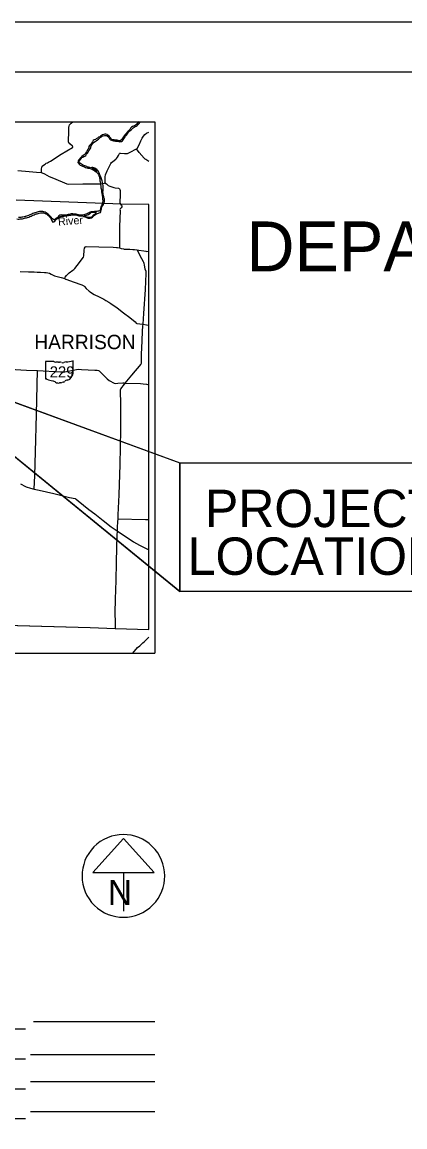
# Model space of a CAD drawing. Extents: x 41.3 to 81.6, y -19.3 to 2.7.
# Drawn here: x 48.93 to 52.78, y -8.35 to 2.73 of the extents above; entities that cross this region are included whole.
import ezdxf

# ---------------------------------------------------------------- set-up
doc = ezdxf.new("R2010")
doc.units = 0
for name, color, linetype in [('Default', 7, 'Continuous'), ('GM_X_County_Road', 7, 'Continuous'), ('GM_X_Major_River', 7, 'Continuous'), ('GM_X_Major_River_Text', 7, 'Continuous'), ('GM_X_State_Route', 7, 'Continuous'), ('GM_X_State_Shield', 7, 'Continuous'), ('GM_X_Township', 7, 'Continuous'), ('GM_X_Township_Road', 7, 'Continuous'), ('GM_X_Township_Text', 7, 'Continuous'), ('GM_X_US_Route', 7, 'Continuous'), ('SH_Border', 7, 'Continuous'), ('SH_Cut_Line', 7, 'Continuous'), ('SH_Data', 7, 'Continuous')]:
    doc.layers.add(name, color=color, linetype=linetype)

msp = doc.modelspace()

# ---------------------------------------------------------------- linework, layer by layer
at = {"layer": 'Default'}
for p, q in [((47.64, -0.634), (50.517, -2.978)), ((47.651, -0.639), (50.517, -1.686))]:
    msp.add_line(p, q, dxfattribs=at)
msp.add_lwpolyline([(47.698, -0.656), (50.517, -1.686), (50.517, -2.978), (47.688, -0.673)], dxfattribs=at)
msp.add_lwpolyline([(50.517, -1.686), (53.875, -1.686), (53.875, -2.978), (50.517, -2.978)], close=True, dxfattribs=at)
at = {"layer": 'GM_X_County_Road'}
for points in [[(48.889, 1.246), (49.003, 1.236), (49.078, 1.23), (49.123, 1.225), (49.128, 1.225), (49.128, 1.26), (49.129, 1.279), (49.13, 1.283), (49.133, 1.288), (49.147, 1.298), (49.164, 1.31), (49.173, 1.317), (49.187, 1.323), (49.197, 1.328), (49.216, 1.339), (49.326, 1.408), (49.438, 1.476), (49.44, 1.479), (49.441, 1.482), (49.438, 1.489), (49.413, 1.513), (49.4, 1.525), (49.397, 1.528), (49.402, 1.647), (49.403, 1.681), (49.403, 1.684), (49.405, 1.691), (49.409, 1.702), (49.417, 1.712), (49.426, 1.72), (49.441, 1.734), (49.441, 1.734)], [(50.204, 1.336), (50.173, 1.356), (50.168, 1.36), (50.158, 1.37), (50.109, 1.426), (50.081, 1.461), (50.086, 1.466), (50.107, 1.504), (50.125, 1.544), (50.136, 1.569), (50.15, 1.588), (50.165, 1.607), (50.18, 1.618), (50.204, 1.629)], [(48.912, 0.232), (48.996, 0.229), (49.053, 0.227), (49.083, 0.226), (49.118, 0.224), (49.158, 0.223), (49.175, 0.223), (49.189, 0.22), (49.208, 0.214), (49.223, 0.206), (49.232, 0.201), (49.243, 0.194), (49.256, 0.189), (49.286, 0.181), (49.326, 0.172), (49.362, 0.163), (49.372, 0.156), (49.383, 0.152), (49.445, 0.129), (49.531, 0.099), (49.545, 0.093), (49.551, 0.089), (49.558, 0.083), (49.577, 0.063), (49.606, 0.035), (49.614, 0.028), (49.62, 0.024), (49.655, 0.002), (49.706, -0.023), (49.753, -0.047), (49.774, -0.058), (49.803, -0.076), (49.822, -0.088), (49.886, -0.134), (49.951, -0.181), (50.014, -0.229), (50.066, -0.274), (50.079, -0.286), (50.085, -0.289), (50.088, -0.29), (50.115, -0.293), (50.143, -0.297), (50.18, -0.302), (50.204, -0.305)], [(48.917, -1.899), (48.966, -1.926), (48.972, -1.928), (49.017, -1.94), (49.055, -1.95), (49.103, -1.961), (49.252, -1.996), (49.408, -2.034), (49.464, -2.046), (49.469, -2.047), (49.475, -2.051), (49.494, -2.067), (49.602, -2.154), (49.662, -2.199), (49.747, -2.265), (49.826, -2.328), (49.885, -2.369), (50.052, -2.479), (50.112, -2.512), (50.204, -2.56)], [(48.645, -3.311), (49.008, -3.322), (49.617, -3.339), (49.866, -3.349), (50.204, -3.358)]]:
    msp.add_lwpolyline(points, dxfattribs=at)
at = {"layer": 'GM_X_Major_River'}
msp.add_line((49.533, 1.386), (49.516, 1.368), dxfattribs=at)
for points in [[(50.106, 1.734), (50.098, 1.725), (50.089, 1.715), (50.082, 1.705), (50.071, 1.699), (50.061, 1.694), (50.051, 1.69), (50.04, 1.685), (50.03, 1.68), (50.021, 1.669), (50.015, 1.658), (50.006, 1.648), (49.996, 1.638), (49.986, 1.629), (49.976, 1.617), (49.966, 1.606), (49.957, 1.594), (49.949, 1.583), (49.942, 1.573), (49.937, 1.563), (49.931, 1.552), (49.921, 1.546), (49.917, 1.544)], [(49.924, 1.535), (49.929, 1.536), (49.939, 1.543), (49.947, 1.554), (49.954, 1.564), (49.962, 1.576), (49.969, 1.588), (49.979, 1.6), (49.987, 1.611), (49.995, 1.621), (50.004, 1.633), (50.014, 1.643), (50.026, 1.654), (50.036, 1.664), (50.046, 1.673), (50.057, 1.679), (50.067, 1.685), (50.078, 1.689), (50.087, 1.696), (50.097, 1.705), (50.106, 1.715), (50.113, 1.725), (50.12, 1.734)], [(49.737, 1.14), (49.733, 1.151), (49.729, 1.161), (49.726, 1.171), (49.721, 1.181), (49.716, 1.192), (49.712, 1.202), (49.708, 1.213), (49.699, 1.234), (49.692, 1.244), (49.684, 1.254), (49.673, 1.262), (49.663, 1.269), (49.654, 1.273), (49.643, 1.274), (49.632, 1.274), (49.622, 1.272), (49.611, 1.274), (49.6, 1.277), (49.59, 1.28), (49.581, 1.284), (49.572, 1.287), (49.561, 1.292), (49.551, 1.295), (49.54, 1.303), (49.529, 1.31), (49.519, 1.316), (49.509, 1.326), (49.504, 1.337), (49.508, 1.348), (49.519, 1.357), (49.524, 1.365), (49.532, 1.376), (49.543, 1.379), (49.552, 1.384), (49.562, 1.388), (49.572, 1.397), (49.579, 1.408), (49.589, 1.419), (49.596, 1.43), (49.603, 1.441), (49.61, 1.452), (49.617, 1.463), (49.621, 1.471), (49.623, 1.481), (49.627, 1.493), (49.632, 1.503), (49.638, 1.514), (49.647, 1.523), (49.658, 1.532), (49.666, 1.536), (49.677, 1.544), (49.688, 1.553), (49.698, 1.56), (49.706, 1.567), (49.717, 1.577), (49.728, 1.584), (49.736, 1.588), (49.747, 1.592), (49.758, 1.595), (49.768, 1.597), (49.778, 1.596), (49.789, 1.591), (49.799, 1.583), (49.807, 1.573), (49.811, 1.563), (49.819, 1.552), (49.83, 1.548), (49.84, 1.547), (49.851, 1.543), (49.86, 1.542), (49.869, 1.54), (49.88, 1.541), (49.892, 1.54), (49.903, 1.536), (49.914, 1.533), (49.924, 1.535)], [(49.917, 1.544), (49.907, 1.543), (49.897, 1.545), (49.887, 1.549), (49.876, 1.551), (49.865, 1.55), (49.855, 1.552), (49.847, 1.553), (49.837, 1.554), (49.826, 1.56), (49.822, 1.571), (49.814, 1.581), (49.805, 1.591), (49.794, 1.6), (49.785, 1.606), (49.774, 1.608), (49.763, 1.609), (49.752, 1.607), (49.741, 1.602), (49.73, 1.595), (49.72, 1.588), (49.711, 1.584), (49.7, 1.578), (49.689, 1.571), (49.677, 1.562), (49.668, 1.557), (49.656, 1.552), (49.646, 1.545), (49.64, 1.534), (49.632, 1.524), (49.626, 1.514), (49.619, 1.505), (49.609, 1.495), (49.603, 1.485), (49.601, 1.475), (49.597, 1.464), (49.592, 1.456), (49.586, 1.445), (49.58, 1.433), (49.573, 1.422), (49.565, 1.411), (49.555, 1.401), (49.544, 1.395), (49.533, 1.386)], [(49.516, 1.368), (49.508, 1.358), (49.499, 1.348), (49.494, 1.338), (49.492, 1.327), (49.497, 1.317), (49.506, 1.307), (49.516, 1.299), (49.526, 1.294), (49.537, 1.289), (49.549, 1.286), (49.56, 1.281), (49.57, 1.276), (49.582, 1.273), (49.593, 1.269), (49.604, 1.268), (49.615, 1.266), (49.626, 1.263), (49.635, 1.259), (49.646, 1.252), (49.654, 1.248), (49.664, 1.241), (49.675, 1.233), (49.684, 1.224), (49.693, 1.215), (49.7, 1.205), (49.702, 1.195), (49.705, 1.184), (49.709, 1.173), (49.712, 1.162)], [(49.684, 1.235), (49.677, 1.247), (49.665, 1.256), (49.653, 1.262), (49.641, 1.268), (49.636, 1.267)], [(49.636, 1.267), (49.641, 1.259), (49.653, 1.251), (49.668, 1.242), (49.68, 1.234), (49.684, 1.235)], [(49.712, 1.162), (49.713, 1.152), (49.714, 1.141), (49.715, 1.133), (49.719, 1.123), (49.72, 1.112), (49.724, 1.08), (49.724, 1.071), (49.726, 1.061), (49.728, 1.05), (49.729, 1.038), (49.73, 1.027), (49.733, 1.016), (49.736, 1.005), (49.737, 0.993), (49.739, 0.983), (49.74, 0.975), (49.74, 0.964), (49.741, 0.956), (49.742, 0.946), (49.742, 0.934), (49.741, 0.926), (49.738, 0.913), (49.734, 0.903), (49.728, 0.892), (49.724, 0.882), (49.722, 0.873), (49.72, 0.863), (49.715, 0.852), (49.711, 0.841), (49.703, 0.837), (49.692, 0.837), (49.681, 0.835), (49.67, 0.834), (49.66, 0.834), (49.648, 0.831), (49.638, 0.83), (49.627, 0.831), (49.616, 0.826), (49.606, 0.819), (49.595, 0.816), (49.584, 0.812), (49.573, 0.807), (49.562, 0.804), (49.552, 0.8), (49.541, 0.797), (49.53, 0.796), (49.519, 0.796), (49.508, 0.798), (49.498, 0.8), (49.486, 0.803), (49.476, 0.806), (49.465, 0.808), (49.443, 0.812), (49.434, 0.812), (49.426, 0.81), (49.416, 0.807), (49.405, 0.805), (49.394, 0.803), (49.385, 0.8), (49.375, 0.798), (49.365, 0.798), (49.354, 0.797), (49.343, 0.798), (49.334, 0.798), (49.323, 0.8), (49.312, 0.798), (49.301, 0.791), (49.293, 0.78), (49.283, 0.771), (49.271, 0.761), (49.26, 0.754), (49.25, 0.751), (49.238, 0.759), (49.232, 0.768), (49.224, 0.778), (49.215, 0.788), (49.205, 0.796), (49.194, 0.806), (49.184, 0.814), (49.173, 0.821), (49.163, 0.826), (49.152, 0.831), (49.141, 0.834), (49.129, 0.835), (49.118, 0.835), (49.107, 0.835), (49.094, 0.831), (49.083, 0.828), (49.072, 0.825), (49.061, 0.821), (49.049, 0.816), (49.041, 0.813), (49.03, 0.808), (49.019, 0.803), (49.01, 0.799), (48.997, 0.795), (48.987, 0.79), (48.975, 0.788), (48.967, 0.784), (48.964, 0.783)], [(49.02, 0.786), (49.022, 0.788), (49.033, 0.793), (49.043, 0.798), (49.053, 0.801), (49.064, 0.806), (49.074, 0.809), (49.084, 0.812), (49.095, 0.815), (49.105, 0.817), (49.116, 0.819), (49.126, 0.821), (49.137, 0.822), (49.147, 0.82), (49.158, 0.817), (49.169, 0.812), (49.179, 0.806), (49.19, 0.798), (49.2, 0.789), (49.211, 0.778), (49.22, 0.768), (49.224, 0.757), (49.229, 0.746), (49.233, 0.736), (49.24, 0.728), (49.251, 0.73), (49.262, 0.738), (49.269, 0.748), (49.28, 0.759), (49.29, 0.763), (49.3, 0.771), (49.31, 0.781), (49.322, 0.787), (49.332, 0.787), (49.343, 0.788), (49.354, 0.787), (49.365, 0.789), (49.377, 0.792), (49.387, 0.794), (49.398, 0.795), (49.41, 0.796), (49.42, 0.798), (49.43, 0.801), (49.441, 0.801), (49.451, 0.802), (49.461, 0.801), (49.469, 0.8), (49.481, 0.798), (49.492, 0.794), (49.503, 0.791), (49.514, 0.791), (49.525, 0.791), (49.535, 0.791), (49.543, 0.79), (49.552, 0.784), (49.563, 0.78), (49.573, 0.777), (49.585, 0.771), (49.595, 0.767), (49.606, 0.767), (49.617, 0.767), (49.628, 0.771), (49.638, 0.777), (49.649, 0.786), (49.658, 0.796), (49.668, 0.804), (49.678, 0.81), (49.688, 0.814), (49.698, 0.817), (49.706, 0.82), (49.718, 0.824), (49.721, 0.833), (49.723, 0.841), (49.725, 0.852), (49.728, 0.861), (49.73, 0.869), (49.732, 0.878), (49.737, 0.887), (49.745, 0.898), (49.75, 0.908), (49.754, 0.919), (49.758, 0.93), (49.76, 0.941), (49.759, 0.953), (49.758, 0.961), (49.757, 0.969), (49.753, 0.98), (49.75, 0.992), (49.747, 1.002), (49.745, 1.013), (49.744, 1.024), (49.744, 1.033), (49.745, 1.043), (49.745, 1.053), (49.745, 1.063), (49.745, 1.085), (49.745, 1.096), (49.744, 1.107), (49.742, 1.116), (49.74, 1.127), (49.737, 1.14)], [(48.881, 0.759), (48.892, 0.758), (48.903, 0.758), (48.914, 0.759), (48.925, 0.76), (48.935, 0.761), (48.945, 0.763), (48.956, 0.766), (48.967, 0.769), (48.978, 0.771), (48.988, 0.775), (49, 0.778), (49.009, 0.782), (49.02, 0.786)], [(48.964, 0.783), (48.953, 0.779), (48.941, 0.776), (48.929, 0.776), (48.918, 0.775), (48.906, 0.773), (48.895, 0.772)], [(49.665, 0.809), (49.68, 0.821), (49.665, 0.825), (49.646, 0.824), (49.623, 0.82), (49.611, 0.81), (49.599, 0.802), (49.577, 0.795), (49.557, 0.789)], [(49.557, 0.789), (49.569, 0.784), (49.587, 0.78), (49.603, 0.776), (49.621, 0.776), (49.638, 0.784), (49.651, 0.799), (49.665, 0.809)]]:
    msp.add_lwpolyline(points, dxfattribs=at)
at = {"layer": 'GM_X_State_Route'}
msp.add_lwpolyline([(48.81, -0.749), (48.978, -0.759), (49.088, -0.762), (49.318, -0.775), (49.337, -0.775), (49.362, -0.773), (49.479, -0.751), (49.497, -0.749), (49.528, -0.75), (49.663, -0.757), (49.687, -0.758), (49.698, -0.762), (49.707, -0.766), (49.787, -0.846), (49.807, -0.862), (49.857, -0.888), (49.869, -0.89), (49.893, -0.889), (49.944, -0.886), (49.953, -0.886), (49.963, -0.887), (50.121, -0.891), (50.148, -0.894), (50.18, -0.899), (50.204, -0.904)], dxfattribs=at)
at = {"layer": 'GM_X_State_Shield'}
for p, q in [((49.166, -0.674), (49.166, -0.843)), ((49.25, -0.671), (49.168, -0.671)), ((49.444, -0.755), (49.444, -0.666)), ((49.444, -0.755), (49.444, -0.755))]:
    msp.add_line(p, q, dxfattribs=at)
for centre, major_axis, start_param, end_param in [((49.345, -0.44), (0.295, 0), 4.814394, 5.042369), ((49.441, -0.666), (0.0031, 0), 6.141152, 7.989035), ((49.169, -0.673), (0.00323, 0), 1.712693, 3.28349), ((49.269, -0.651), (0.0313, 0), 4.042523, 4.731795), ((49.28, -0.766), (0.112, 0), 1.404758, 1.657858), ((49.305, -0.672), (0.00903, 0), 3.836095, 5.185415), ((49.318, -0.692), (0.0188, 0), 0.950623, 2.079405), ((49.343, -0.665), (0.0226, 0), 4.081561, 5.145723), ((49.382, -0.722), (0.0594, 0), 1.699011, 2.107814), ((49.443, -0.761), (0.0048, 0), 1.883978, 3.671073), ((49.413, -0.773), (0.0288, 0), 5.934695, 6.695948), ((49.441, -0.755), (0.00332, 0), 5.05454, 6.418171), ((49.169, -0.843), (0.00325, 0), 3.00124, 4.508301), ((49.169, -0.826), (0.0248, 0), 4.665946, 4.897461), ((49.174, -0.852), (0.00895, 0), 0.519207, 1.627899), ((49.287, -0.7), (0.213, 0), 4.195997, 4.488961), ((49.224, -0.919), (0.0667, 0), 0.823519, 1.323587), ((49.296, -0.853), (0.0423, 0), 4.026481, 4.996735), ((49.32, -0.912), (0.0348, 0), 1.495662, 1.94098), ((49.323, -0.866), (0.0226, 0), 4.691044, 5.507374), ((49.344, -0.882), (0.00635, 0), 1.147584, 2.315152), ((49.341, -0.859), (0.0239, 0), 4.937069, 5.64225), ((49.392, -0.89), (0.0404, 0), 1.647645, 2.488434), ((49.361, -0.803), (0.0739, 0), 5.101752, 6.440018), ((49.455, -0.792), (0.021, 0), 2.387724, 3.262537)]:
    msp.add_ellipse(centre, major_axis=major_axis, ratio=0.8, start_param=start_param, end_param=end_param, dxfattribs=at)
at = {"layer": 'GM_X_Township'}
msp.add_lwpolyline([(48.645, -3.311), (49.617, -3.339), (49.866, -3.349), (50.204, -3.358), (50.204, 0.905), (49.92, 0.909), (49.843, 0.912), (48.873, 0.949)], dxfattribs=at)
at = {"layer": 'GM_X_Township_Road'}
for points in [[(49.764, 1.121), (49.766, 1.125), (49.767, 1.135), (49.765, 1.176), (49.765, 1.183), (49.771, 1.2), (49.786, 1.242), (49.799, 1.269), (49.824, 1.316), (49.83, 1.324), (49.843, 1.336), (49.872, 1.358), (49.881, 1.366), (49.891, 1.38), (49.899, 1.394), (49.906, 1.41), (49.909, 1.415), (49.913, 1.418), (49.919, 1.419), (49.961, 1.417), (49.984, 1.416), (49.992, 1.417), (50.018, 1.428), (50.081, 1.461)], [(49.128, 1.225), (49.134, 1.223), (49.158, 1.21), (49.205, 1.184), (49.23, 1.174), (49.335, 1.13), (49.381, 1.112), (49.385, 1.11), (49.402, 1.109), (49.543, 1.111), (49.679, 1.112), (49.725, 1.113), (49.747, 1.115), (49.76, 1.118), (49.764, 1.121)], [(49.764, 1.121), (49.779, 1.11), (49.792, 1.099), (49.796, 1.096), (49.813, 1.089), (49.843, 1.077), (49.852, 1.073), (49.867, 1.07), (49.9, 1.067), (49.907, 1.065), (49.911, 1.062), (49.915, 1.056), (49.916, 1.043), (49.918, 0.988), (49.915, 0.938), (49.914, 0.927), (49.915, 0.919), (49.92, 0.909), (49.927, 0.899)], [(49.927, 0.899), (49.929, 0.897), (49.933, 0.889), (49.935, 0.882), (49.935, 0.879), (49.926, 0.871), (49.917, 0.862), (49.915, 0.853), (49.916, 0.844), (49.911, 0.68), (49.911, 0.536), (49.91, 0.468)], [(49.362, 0.163), (49.365, 0.175), (49.377, 0.193), (49.406, 0.22), (49.441, 0.244), (49.452, 0.252), (49.462, 0.263), (49.51, 0.321), (49.546, 0.372), (49.549, 0.377), (49.551, 0.388), (49.557, 0.446), (49.559, 0.465), (49.564, 0.476), (49.567, 0.479), (49.574, 0.482), (49.703, 0.48), (49.847, 0.476), (49.881, 0.474), (49.891, 0.472), (49.91, 0.468), (49.927, 0.464), (49.949, 0.458), (49.957, 0.456), (49.992, 0.455), (50.013, 0.455), (50.043, 0.454), (50.061, 0.452), (50.086, 0.448), (50.104, 0.446), (50.153, 0.439), (50.175, 0.435), (50.183, 0.434), (50.204, 0.436)], [(50.086, 0.448), (50.1, 0.42), (50.13, 0.363), (50.146, 0.332), (50.15, 0.324), (50.153, 0.316), (50.157, 0.296), (50.166, 0.26), (50.173, 0.235), (50.173, 0.223), (50.174, 0.211), (50.167, 0.05), (50.152, -0.19), (50.143, -0.297)], [(50.143, -0.297), (50.14, -0.318), (50.138, -0.366), (50.133, -0.464), (50.129, -0.599), (50.127, -0.686), (50.127, -0.692), (50.123, -0.698), (50.032, -0.807), (49.963, -0.887)], [(49.055, -1.95), (49.06, -1.813), (49.068, -1.576), (49.077, -1.202), (49.082, -0.905), (49.088, -0.762)], [(49.963, -0.887), (49.948, -0.91), (49.93, -0.931), (49.923, -0.942), (49.919, -0.949), (49.916, -0.958), (49.916, -0.972), (49.919, -1.09), (49.919, -1.356), (49.913, -1.705), (49.903, -2.008), (49.894, -2.21), (49.892, -2.253), (49.89, -2.275), (49.886, -2.335), (49.885, -2.369), (49.884, -2.416), (49.88, -2.537), (49.877, -2.687), (49.872, -2.866), (49.867, -3.054), (49.864, -3.192), (49.867, -3.29), (49.866, -3.349)], [(50.204, -2.26), (50.172, -2.259), (49.892, -2.253)]]:
    msp.add_lwpolyline(points, dxfattribs=at)
at = {"layer": 'GM_X_US_Route'}
msp.add_lwpolyline([(50.044, -3.595), (50.092, -3.541), (50.113, -3.523), (50.145, -3.494), (50.16, -3.479), (50.201, -3.439), (50.204, -3.435)], dxfattribs=at)
at = {"layer": 'SH_Border'}
msp.add_lwpolyline([(42.765, 2.234), (74.765, 2.234), (74.765, -18.766), (42.765, -18.766)], close=True, dxfattribs=at)
at = {"layer": 'SH_Cut_Line'}
msp.add_lwpolyline([(41.265, -19.266), (75.265, -19.266), (75.265, 2.734), (41.265, 2.734)], close=True, dxfattribs=at)
at = {"layer": 'SH_Data'}
for p, q in [((43.265, 1.734), (50.265, 1.734)), ((50.265, 1.734), (50.265, -3.595)), ((43.265, -3.595), (50.265, -3.595)), ((49.949, -5.457), (49.641, -5.798)), ((50.257, -5.798), (49.949, -5.457)), ((49.641, -5.798), (50.257, -5.798)), ((49.949, -5.798), (49.949, -6.185)), ((49.949, -5.831), (49.949, -5.831)), ((49.949, -5.831), (49.949, -5.831)), ((49.047, -7.29), (50.265, -7.29)), ((48.965, -7.369), (46.158, -7.369)), ((50.265, -7.625), (49.015, -7.625)), ((48.965, -7.669), (45.654, -7.669)), ((48.965, -7.969), (45.15, -7.969)), ((50.265, -7.896), (49.015, -7.896)), ((50.265, -8.196), (49.015, -8.196)), ((48.965, -8.269), (44.909, -8.269))]:
    msp.add_line(p, q, dxfattribs=at)
msp.add_arc((49.949, -5.831), 0.415, 129.7798, 129.7633, dxfattribs=at)

# ---------------------------------------------------------------- texts
at = {"layer": 'Default'}
for s, height, p in [('DEPARTMENT OF TRANSPORTATION', 0.5, (51.184, 0.234)), ('PROJECT ', 0.375, (50.768, -2.332)), ('LOCATION ', 0.375, (50.595, -2.811))]:
    msp.add_text(s, height=height, dxfattribs=at).set_placement(p)
at = {"layer": 'GM_X_Major_River_Text'}
msp.add_text('River', height=0.08, rotation=4.2126, dxfattribs=at).set_placement((49.296, 0.692))
at = {"layer": 'GM_X_State_Shield'}
msp.add_text('229', height=0.1114, dxfattribs=at).set_placement((49.209, -0.831))
at = {"layer": 'GM_X_Township_Text'}
msp.add_text('HARRISON', height=0.144, rotation=0, dxfattribs=at).set_placement((49.055, -0.547))
at = {"layer": 'SH_Data'}
msp.add_text('N', height=0.25, dxfattribs=at).set_placement((49.794, -6.122))

doc.saveas('drawing.dxf')
